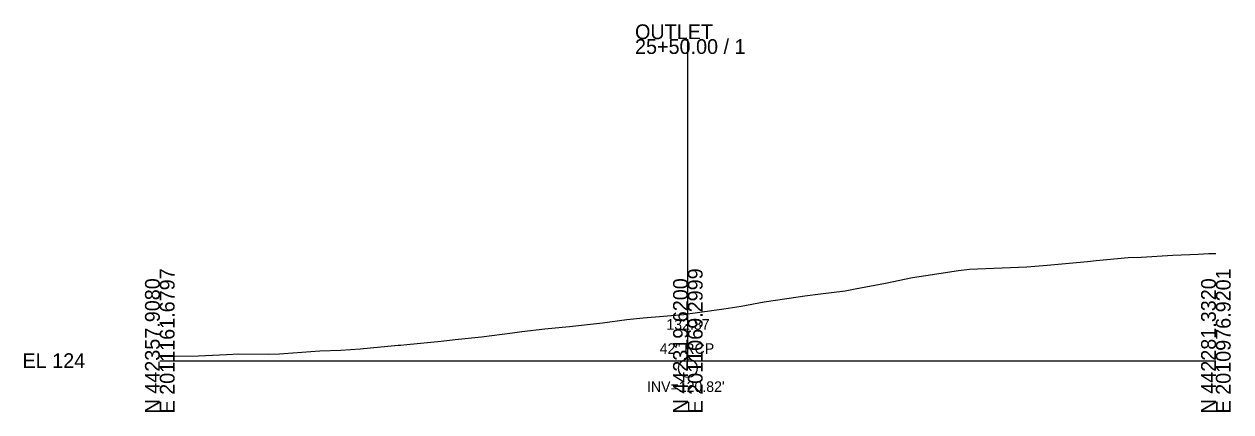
# Model space of a CAD drawing. Extents: x -26 to 1203, y -15 to 9526.
# Drawn here: x 974.3 to 1202.8, y 5490.3 to 5563.7 of the extents above; entities that cross this region are included whole.
import ezdxf

# ---------------------------------------------------------------- set-up
doc = ezdxf.new("R2010")
doc.units = 0
for name, color, linetype in [('Exist Cross Section Cell', 7, 'Continuous'), ('Exist XS Center Line Elevation Label', 7, 'Continuous'), ('Exist XS Ground Line', 7, 'Continuous'), ('Prop XSC Text', 7, 'Continuous')]:
    doc.layers.add(name, color=color, linetype=linetype)

msp = doc.modelspace()

# ---------------------------------------------------------------- linework, layer by layer
at = {"layer": 'Exist Cross Section Cell'}
for p, q in [((1100, 5500), (1100, 5560.89)), ((1000, 5500), (1100, 5500)), ((1100, 5500), (1200, 5500))]:
    msp.add_line(p, q, dxfattribs=at)
at = {"layer": 'Exist XS Ground Line'}
msp.add_lwpolyline([(1000, 5500.87), (1001.82, 5500.88), (1007.34, 5500.94), (1012.64, 5501.16), (1014.99, 5501.31), (1020.65, 5501.26), (1022.64, 5501.32), (1023.47, 5501.36), (1030.3, 5501.87), (1034.29, 5501.98), (1037.95, 5502.26), (1045.12, 5502.92), (1045.6, 5502.96), (1046.77, 5503.07), (1053.26, 5503.7), (1055.94, 5503.99), (1060.91, 5504.53), (1066.77, 5505.3), (1068.56, 5505.51), (1072.89, 5506), (1076.21, 5506.34), (1077.59, 5506.5), (1083.87, 5507.18), (1088.42, 5507.78), (1091.52, 5508.1), (1099.24, 5508.77), (1100, 5508.87), (1106.83, 5509.8), (1110.07, 5510.34), (1114.48, 5511.12), (1120.89, 5512.12), (1122.13, 5512.27), (1125.13, 5512.67), (1129.79, 5513.25), (1131.72, 5513.61), (1137.44, 5514.66), (1142.54, 5515.74), (1145.09, 5516.12), (1151.24, 5517.07), (1153.37, 5517.32), (1154.87, 5517.4), (1164.19, 5517.77), (1168.05, 5518.07), (1175.02, 5518.74), (1175.7, 5518.81), (1177.36, 5519), (1183.36, 5519.53), (1185.84, 5519.63), (1191.84, 5519.96), (1196.67, 5520.2), (1198.66, 5520.27), (1200, 5520.3)], dxfattribs=at)
at = {"layer": 'Prop XSC Text'}
msp.add_circle((1100, 5498.57), 1.75, dxfattribs=at)

# ---------------------------------------------------------------- texts
at = {"layer": 'Exist Cross Section Cell'}
for s, p in [('OUTLET', (1090, 5560.89)), ('25+50.00 / 1', (1090, 5558.09)), ('EL 124', (974, 5498.6))]:
    msp.add_text(s, height=2.8, dxfattribs=at).set_placement(p)
for s, p in [('E 2011161.6797', (1002.8, 5490)), ('E 2011069.2999', (1102.8, 5490)), ('E 2010976.9201', (1202.8, 5490)), ('N 442357.9080', (1000, 5490)), ('N 442319.6200', (1100, 5490)), ('N 442281.3320', (1200, 5490))]:
    msp.add_text(s, height=2.8, rotation=90, dxfattribs=at).set_placement(p)
at = {"layer": 'Exist XS Center Line Elevation Label'}
msp.add_text('132.87', height=2, dxfattribs=at).set_placement((1095.94, 5505.87))
at = {"layer": 'Prop XSC Text'}
for s, p in [('42" RCP', (1094.67, 5501.29)), ("INV=120.82'", (1092.26, 5494.08))]:
    msp.add_text(s, height=2, dxfattribs=at).set_placement(p)

doc.saveas('drawing.dxf')
